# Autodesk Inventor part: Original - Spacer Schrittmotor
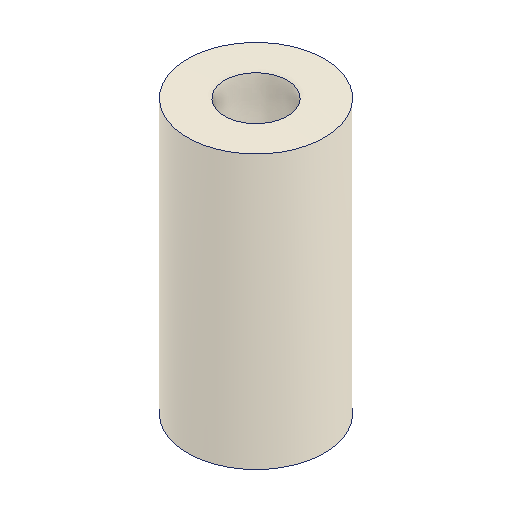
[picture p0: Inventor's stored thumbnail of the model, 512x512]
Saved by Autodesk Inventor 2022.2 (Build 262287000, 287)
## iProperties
Created: 2024-09
Part Number: Original - Spacer Schrittmotor
Material: Generico
Document SubType Name: Modeling
Designer: 18907419
Density: 1 g/cm^3
Appearance: Default
Author: 18907419
Revision Number: ANY
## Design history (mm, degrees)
feature "Aufsatz-Linear austragen1"
node "Solido1"
